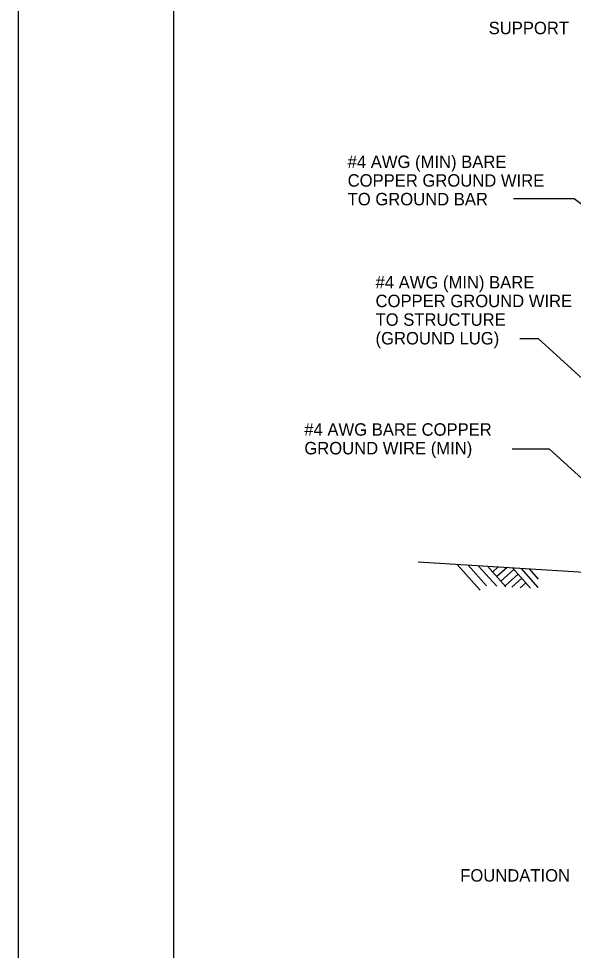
# Model space of a CAD drawing. Extents: x 1299104.8 to 1299141.6, y 239639.8 to 239661.8.
# Drawn here: x 1299104.8 to 1299110.16, y 239647.52 to 239656.51 of the extents above; entities that cross this region are included whole.
import ezdxf

# ---------------------------------------------------------------- set-up
doc = ezdxf.new("R2010")
doc.units = 0
for name, color, linetype in [('DIM TXT', 7, 'Continuous'), ('GS_plotshape_p', 7, 'Continuous'), ('Level 1', 7, 'Continuous')]:
    doc.layers.add(name, color=color, linetype=linetype)

msp = doc.modelspace()

# ---------------------------------------------------------------- linework, layer by layer
at = {"layer": 'DIM TXT'}
for p, q in [((1299108.6592, 239651.2669), (1299110.878, 239651.1315)), ((1299109.2593, 239650.9936), (1299109.0363, 239651.2438)), ((1299109.3199, 239651.0384), (1299109.1425, 239651.2374)), ((1299109.4192, 239651.0324), (1299109.2418, 239651.2313)), ((1299109.5073, 239651.0273), (1299109.3302, 239651.2259)), ((1299109.4347, 239651.2195), (1299109.3797, 239651.1704)), ((1299109.5188, 239651.2144), (1299109.42, 239651.1262)), ((1299109.5856, 239651.1949), (1299109.4583, 239651.0813)), ((1299109.6267, 239651.1489), (1299109.5002, 239651.0361)), ((1299109.7472, 239651.0136), (1299109.5711, 239651.2112)), ((1299109.8192, 239651.0217), (1299109.6547, 239651.2061)), ((1299109.8242, 239651.1018), (1299109.7356, 239651.2012)), ((1299109.6616, 239651.1096), (1299109.5656, 239651.024)), ((1299109.7009, 239651.0655), (1299109.6461, 239651.0166))]:
    msp.add_line(p, q, dxfattribs=at)
for points in [[(1299112.1765, 239653.2764), (1299110.1659, 239654.7692), (1299109.5805, 239654.7692)], [(1299111.4841, 239651.9115), (1299109.8244, 239653.4184), (1299109.6414, 239653.4184)], [(1299111.628, 239650.8137), (1299109.9288, 239652.3566), (1299109.5698, 239652.3566)]]:
    msp.add_lwpolyline(points, dxfattribs=at)
at = {"layer": 'GS_plotshape_p'}
msp.add_lwpolyline([(1299104.8019, 239661.7913), (1299138.8019, 239661.7913), (1299138.8019, 239639.7913), (1299104.8019, 239639.7913)], close=True, dxfattribs=at)
at = {"layer": 'Level 1'}
msp.add_lwpolyline([(1299138.3019, 239640.2913), (1299106.3019, 239640.2913), (1299106.3019, 239661.2913), (1299138.3019, 239661.2913)], close=True, dxfattribs=at)

# ---------------------------------------------------------------- texts
at = {"layer": 'DIM TXT'}
for s, p in [('SUPPORT', (1299109.3418, 239656.3588)), ('#4 AWG (MIN) BARE', (1299107.9797, 239655.0677)), ('COPPER GROUND WIRE ', (1299107.9797, 239654.8877)), ('TO GROUND BAR', (1299107.9797, 239654.7077)), ('#4 AWG (MIN) BARE', (1299108.2492, 239653.9056)), ('COPPER GROUND WIRE', (1299108.2492, 239653.7256)), ('TO STRUCTURE', (1299108.2492, 239653.5456)), ('(GROUND LUG)', (1299108.2492, 239653.3656)), ('#4 AWG BARE COPPER', (1299107.5613, 239652.4852)), ('GROUND WIRE (MIN)', (1299107.5613, 239652.3052)), ('FOUNDATION', (1299109.067, 239648.1836))]:
    msp.add_text(s, height=0.12, dxfattribs=at).set_placement(p)

doc.saveas('drawing.dxf')
